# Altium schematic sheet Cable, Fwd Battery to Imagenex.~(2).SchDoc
size Tabloid; Organization: Monterey Bay Aquarium Research Institute; Address1: 7700 Sandholdt Rd; Address2: Moss Landing, CA 95039-9644; CompanyName: MBARI; DrawnBy: Hans Thomas; Engineer: Hans Thomas
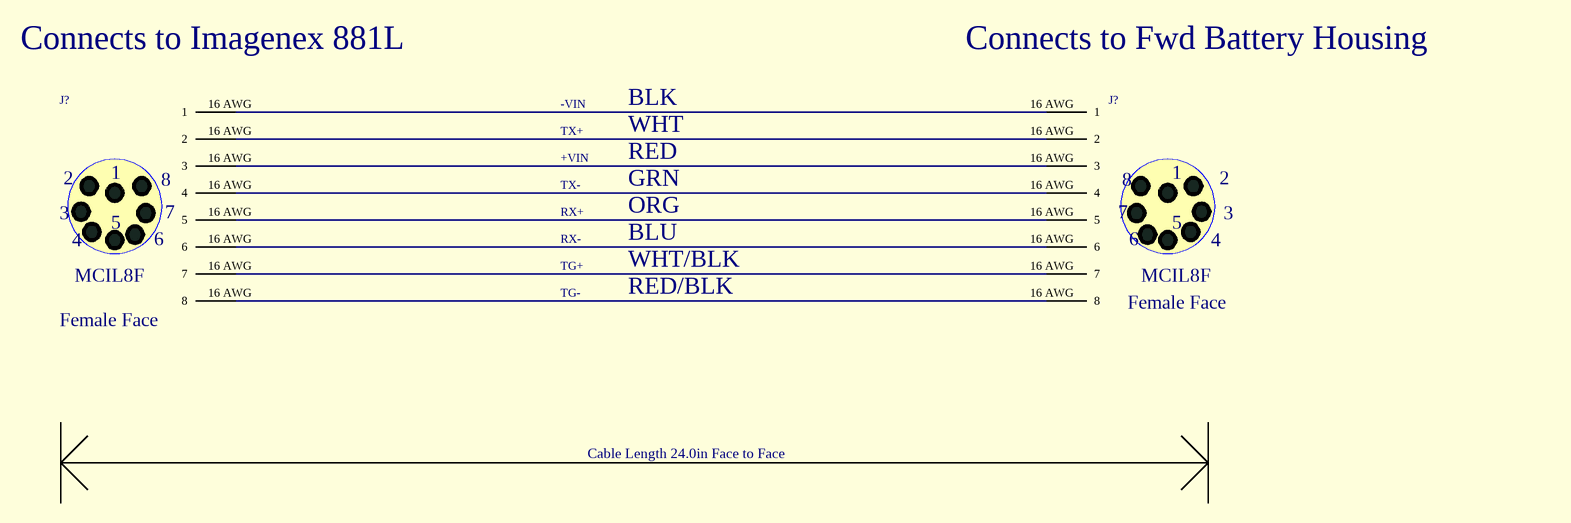
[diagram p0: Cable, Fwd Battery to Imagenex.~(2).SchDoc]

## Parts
(Parts that share a designator on the sheet are numbered #1, #2 ... from top to bottom, then left to right.)
J?#1  MCIL8F  View: Female Face
J?#2  MCIL8F  View: Female Face

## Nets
NetJ?#1_16 AWG: J?#1.16_AWG(1) J?#2.16_AWG(1)
NetJ?#1_16 AWG: J?#1.16_AWG(2) J?#2.16_AWG(2)  [a separate net that carries the same name]
NetJ?#1_16 AWG: J?#1.16_AWG(3) J?#2.16_AWG(3)  [a separate net that carries the same name]
NetJ?#1_16 AWG: J?#1.16_AWG(4) J?#2.16_AWG(4)  [a separate net that carries the same name]
NetJ?#1_16 AWG: J?#1.16_AWG(5) J?#2.16_AWG(5)  [a separate net that carries the same name]
NetJ?#1_16 AWG: J?#1.16_AWG(6) J?#2.16_AWG(6)  [a separate net that carries the same name]
NetJ?#1_16 AWG: J?#1.16_AWG(7) J?#2.16_AWG(7)  [a separate net that carries the same name]
NetJ?#1_16 AWG: J?#1.16_AWG(8) J?#2.16_AWG(8)  [a separate net that carries the same name]

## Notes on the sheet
- Connects to Imagenex 881L
- Connects to Fwd Battery Housing
- -VIN
- TX+
- BLK
- WHT
- +VIN
- TX-
- RED
- GRN
- RX+
- RX-
- TG+
- ORG
- BLU
- WHT/BLK
- TG-
- RED/BLK
- Cable Length 24.0in Face to Face

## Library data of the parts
J?#1 J?#2 = SUBCONN-MCxx8F: Subconn MCIL8F Connector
